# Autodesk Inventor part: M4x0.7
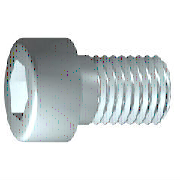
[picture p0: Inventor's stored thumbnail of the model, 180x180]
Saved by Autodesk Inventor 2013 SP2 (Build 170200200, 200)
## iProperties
IsCustomPart: 1
Created: 2009-02
Part Number: M4x0.7
Material: 강, 연강
Description: 6각머리 태핑 나사
Document SubType Name: Modeling
Standard: KS B 1003
Designer: SeoGD™[esajin.kr]
Standards Organization: KS
Language: ko-KR
Size Designation: M 4 x 16
Categories: <MemberInstance><Categories><Category DisplayName="조임쇠" InternalName="e4da775c-781d-43d5-af7c-5136215cf5a6" Mnemonic="FSTN"><Category DisplayName="볼트" InternalN
Density: 7.86 g/cm^3
Mass: 2.62973 g
Surface Area: 3.81118 cm^2
Volume: 0.334572 cm^3
Author: SeoGD™[esajin.kr]
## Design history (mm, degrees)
sketch "스케치1"
  geometry: L1 (-1, 0)-(16, 0); L2 (16, 0)-(16, 2); L3 (16, 2)-(1.75, 2); L4 (1.75, 2)-(1.32, 2); L5 (1.32, 2)-(0, 2); L6 (0, 2)-(0, 3.5); L7 (0, 3.5)-(-4, 3.5); L8 (-4, 3.5)-(-4, 1.732); L9 (-4, 1.732)-(-2, 1.732); L10 (-2, 1.732)-(-1, 0); L11 (-8, 0)-(20, 0) reference; L12 (0, -0.7)-(0, 4.2) reference; L13 (1.75, 2)-(0, 2)
  constraints: 22 end point, 6 parallel, 2 collinear, 2 perpendicular, 1 horizontal, 1 point on line
  dimensions: "d1" = 14.25 distance from line of L3.end L2 (= GEL); "d2" = 0.42952 distance of L4.end L3.end (computed from GAL); "d3" = 4 distance between parallel lines of L8 L6 (= KOH); "d4" = 2 distance of L8.end L9.end (= INTI); "d5" = 60 deg angle of L10 L1; "d6" = 4 diameter of L3 L1 (= GD); "d7" = 4 diameter of L5 L1 (= BDM); "d8" = 3.4641 diameter of L9 L1 (= 1.1547 x SW); "d9" = 7 diameter of L7 L1 (= KOD); "d26" = 16 distance between parallel lines of L12 L2 (= NLG)
revolve "본체" sketch "스케치1" stored, may be unused: angle "d10" = 90 deg
sketch "스케치2"
  geometry: L1 (0, -4.9)-(0, 4.9) reference; L2 (-4.9, 0)-(4.9, 0) reference; L3 (1.732, 0)-(0.866, -1.5); L4 (0.866, -1.5)-(-0.866, -1.5); L5 (-0.866, -1.5)-(-1.732, 0); L6 (-1.732, 0)-(-0.866, 1.5); L7 (-0.866, 1.5)-(0.866, 1.5); L8 (0.866, 1.5)-(1.732, 0); 2 further points
  constraints: 12 end point, 1 coincident, 1 horizontal alignment, 1 point on line, 12 other
extrude "슬롯" join sketch "스케치2" stored distance "d11" = 10; taper "d12" = 0 deg
workplane "Work Plane1"
fillet "Fillet2" dims "d30" = 0.1 (= R)
body "Solid1"
fillet "모깎기1" dims "d17" = 0.4 (= RR)
feature "스레드" dims "d13" = 14.25 (= GEL), "d14" = 0
chamfer "모따기1" distance "d15" = 0.42941 (= -0.5 x SPD + 0.5 x GD); stored, may be unused: second distance "d16" = 0.42941 (= GUL), angle "d27" = 45 deg
other parameters: "GD" = 4 (= NND) [user parameter; used in 2 equation terms], "NLG" = 16 [user parameter; used in 1 equation term], "GEL" = 14.25 [user parameter; used in 2 equation terms], "KOD" = 7 [user parameter; used in 1 equation term], "KOH" = 4 [user parameter; used in 1 equation term], "INTI" = 2 [user parameter; used in 1 equation term], "GAL" = 0.42941 (= 0.61345 x PTC) [user parameter; used in 1 equation term], "GUL" = 0.42941 (= 0.61345 x PTC) [user parameter; used in 1 equation term], "BDM" = 4 (= NND) [user parameter; used in 1 equation term], "SW" = 3 [user parameter; used in 2 equation terms], "RR" = 0.4 [user parameter; used in 1 equation term], "SPD" = 3.14117 (= NND - 1.2269 x PTC) [user parameter; used in 1 equation term], "d19" = 0, "d28" = 0, "d29" = 0, "R" = 0.1 [user parameter; used in 1 equation term], "PHH" = 0.2 [user parameter], "GD1" = 3.14117 (= THREADDIA - 1.2269 x PTC) [user parameter], "THREADDIA" = 4 [user parameter; used in 1 equation term], "FAWI" = 45 deg [user parameter], "TPU" = 14.28571 (computed from PTC) [user parameter], "PTC" = 0.7 [user parameter; used in 5 equation terms], "NND" = 4 [user parameter; used in 3 equation terms], "TOA" = 30 deg [user parameter], "E0" = 3.465 (= 1.155 x SW) [user parameter]
